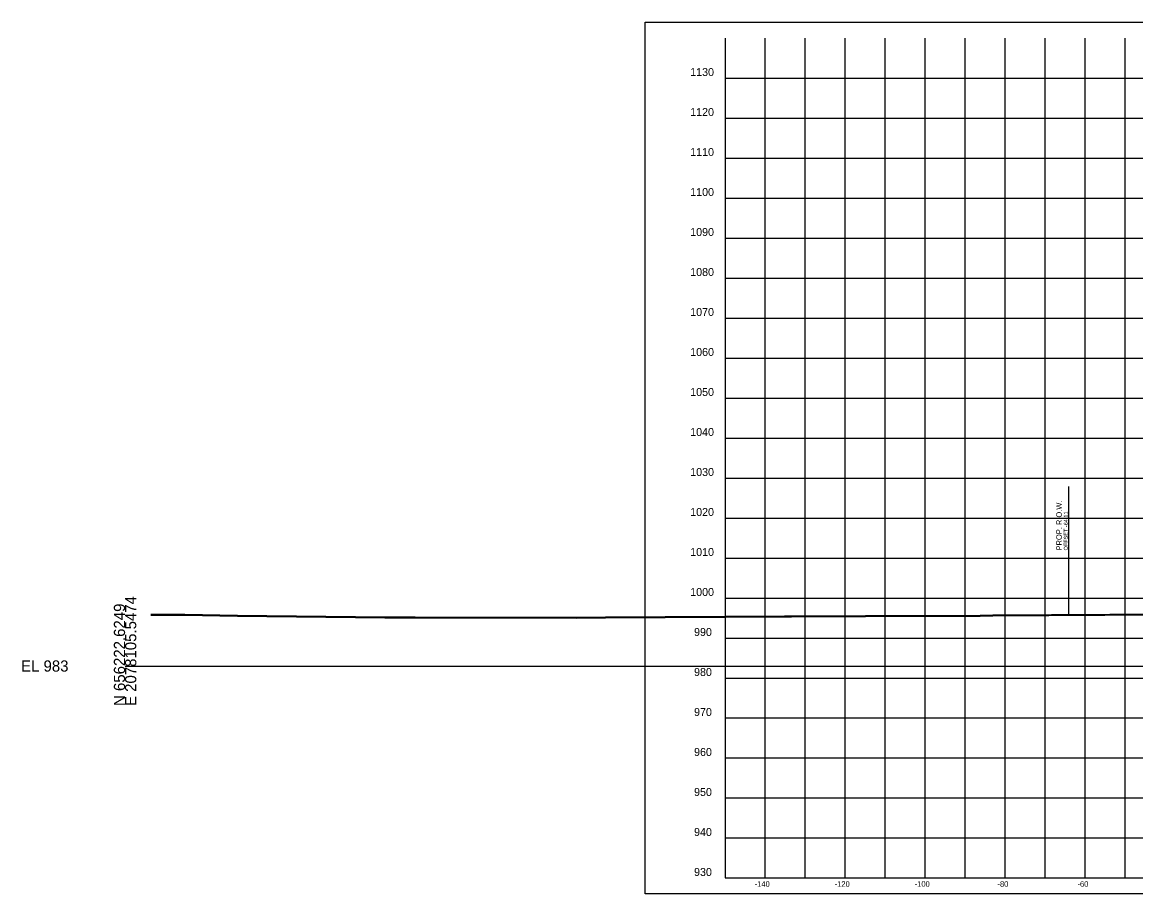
# Model space of a CAD drawing. Extents: x 5868 to 6683, y 2883 to 19120.
# Drawn here: x 5868.1 to 6146.4, y 12888.1 to 13106 of the extents above; entities that cross this region are included whole.
import ezdxf

# ---------------------------------------------------------------- set-up
doc = ezdxf.new("R2010")
doc.units = 0
for name, color, linetype in [('DESIGN - ROW - Right-of-Way and Easement Labels', 7, 'Continuous'), ('DESIGN - ROW - Right-of-Way Linework', 7, 'Continuous'), ('DESIGN - SHEET - Corner Text', 7, 'Continuous'), ('DESIGN - SHEET - Light Grid', 7, 'Continuous'), ('DESIGN - SHEET - Linework', 7, 'Continuous'), ('DESIGN - SHEET - Plot Shape', 7, 'Continuous'), ('SURVEY - GROUND - Bottom of Topsoil Layer', 7, 'Continuous'), ('SURVEY - GROUND - Top of Ground', 7, 'Continuous')]:
    doc.layers.add(name, color=color, linetype=linetype)

msp = doc.modelspace()

# ---------------------------------------------------------------- linework, layer by layer
at = {"layer": 'DESIGN - ROW - Right-of-Way Linework'}
msp.add_line((6129.67, 12957.96), (6129.67, 12989.96), dxfattribs=at)
at = {"layer": 'DESIGN - SHEET - Light Grid'}
msp.add_line((5893.78, 12945.07), (6193.78, 12945.07), dxfattribs=at)
at = {"layer": 'DESIGN - SHEET - Linework'}
for p, q in [((6053.78, 12892.07), (6053.78, 13102.07)), ((6063.78, 12892.07), (6063.78, 13102.07)), ((6073.78, 12892.07), (6073.78, 13102.07)), ((6083.78, 12892.07), (6083.78, 13102.07)), ((6093.78, 12892.07), (6093.78, 13102.07)), ((6103.78, 12892.07), (6103.78, 13102.07)), ((6113.78, 12892.07), (6113.78, 13102.07)), ((6123.78, 12892.07), (6123.78, 13102.07)), ((6133.78, 12892.07), (6133.78, 13102.07)), ((6143.78, 12892.07), (6143.78, 13102.07)), ((6043.78, 13092.07), (6343.78, 13092.07)), ((6043.78, 13082.07), (6343.78, 13082.07)), ((6043.78, 13072.07), (6343.78, 13072.07)), ((6043.78, 13062.07), (6343.78, 13062.07)), ((6043.78, 13052.07), (6343.78, 13052.07)), ((6043.78, 13042.07), (6343.78, 13042.07)), ((6043.78, 13032.07), (6343.78, 13032.07)), ((6043.78, 13022.07), (6343.78, 13022.07)), ((6043.78, 13012.07), (6343.78, 13012.07)), ((6043.78, 13002.07), (6343.78, 13002.07)), ((6043.78, 12992.07), (6343.78, 12992.07)), ((6043.78, 12982.07), (6343.78, 12982.07)), ((6043.78, 12972.07), (6343.78, 12972.07)), ((6043.78, 12962.07), (6343.78, 12962.07)), ((6043.78, 12952.07), (6343.78, 12952.07)), ((6043.78, 12942.07), (6343.78, 12942.07)), ((6043.78, 12932.07), (6343.78, 12932.07)), ((6043.78, 12922.07), (6343.78, 12922.07)), ((6043.78, 12912.07), (6343.78, 12912.07)), ((6043.78, 12902.07), (6343.78, 12902.07))]:
    msp.add_line(p, q, dxfattribs=at)
msp.add_lwpolyline([(6043.78, 13102.07), (6043.78, 12892.07), (6343.78, 12892.07), (6343.78, 13102.07)], dxfattribs=at)
at = {"layer": 'DESIGN - SHEET - Plot Shape'}
msp.add_lwpolyline([(6023.78, 13106.01), (6363.78, 13106.01), (6363.78, 12888.13), (6023.78, 12888.13)], close=True, dxfattribs=at)
at = {"layer": 'SURVEY - GROUND - Bottom of Topsoil Layer'}
for p, q in [((5900.23, 12957.75), (5908.74, 12957.75)), ((5908.74, 12957.75), (5921.88, 12957.55)), ((6110.69, 12957.6), (6154.54, 12957.85)), ((5921.88, 12957.55), (5958.67, 12957.13)), ((5958.67, 12957.13), (5966.3, 12957.1)), ((5966.3, 12957.1), (6006.64, 12957.07)), ((6006.64, 12957.07), (6013.9, 12957.08)), ((6013.9, 12957.08), (6058.64, 12957.33)), ((6058.64, 12957.33), (6060.34, 12957.35)), ((6060.34, 12957.35), (6078.82, 12957.43)), ((6078.82, 12957.43), (6107.49, 12957.55)), ((6107.49, 12957.55), (6110.69, 12957.6))]:
    msp.add_line(p, q, dxfattribs=at)
at = {"layer": 'SURVEY - GROUND - Top of Ground'}
msp.add_lwpolyline([(5900.23, 12958), (5908.74, 12958), (5921.88, 12957.8), (5958.67, 12957.38), (5966.3, 12957.35), (6006.64, 12957.32), (6013.9, 12957.33), (6058.64, 12957.58), (6060.34, 12957.6), (6078.82, 12957.68), (6107.49, 12957.8), (6110.69, 12957.85), (6154.54, 12958.1)], dxfattribs=at)

# ---------------------------------------------------------------- texts
at = {"layer": 'DESIGN - ROW - Right-of-Way and Easement Labels'}
for s, height, p in [('PROP. R.O.W.', 1.4, (6127.92, 12973.96)), ('OFFSET -64.11', 1, (6129.42, 12973.96))]:
    msp.add_text(s, height=height, rotation=90, dxfattribs=at).set_placement(p)
at = {"layer": 'DESIGN - SHEET - Corner Text'}
for s, height, p in [('1130', 2, (6035.03, 13092.57)), ('1120', 2, (6035.03, 13082.57)), ('1110', 2, (6035.03, 13072.57)), ('1100', 2, (6035.03, 13062.57)), ('1090', 2, (6035.03, 13052.57)), ('1080', 2, (6035.03, 13042.57)), ('1070', 2, (6035.03, 13032.57)), ('1060', 2, (6035.03, 13022.57)), ('1050', 2, (6035.03, 13012.57)), ('1040', 2, (6035.03, 13002.57)), ('1030', 2, (6035.03, 12992.57)), ('1020', 2, (6035.03, 12982.57)), ('1010', 2, (6035.03, 12972.57)), ('1000', 2, (6035.03, 12962.57)), ('990', 2, (6036, 12952.57)), ('980', 2, (6036, 12942.57)), ('970', 2, (6036, 12932.57)), ('960', 2, (6036, 12922.57)), ('950', 2, (6036, 12912.57)), ('940', 2, (6036, 12902.57)), ('930', 2, (6036, 12892.57)), ('-140', 1.4, (6051.16, 12889.87)), ('-120', 1.4, (6071.16, 12889.87)), ('-100', 1.4, (6091.16, 12889.87)), ('-80', 1.4, (6111.84, 12889.87)), ('-60', 1.4, (6131.84, 12889.87))]:
    msp.add_text(s, height=height, dxfattribs=at).set_placement(p)
at = {"layer": 'DESIGN - SHEET - Light Grid'}
for s, p in [('N 656222.6249', (5893.78, 12935.07)), ('E 2078105.5474', (5896.58, 12935.07))]:
    msp.add_text(s, height=2.8, rotation=90, dxfattribs=at).set_placement(p)
msp.add_text('EL 983', height=2.8, dxfattribs=at).set_placement((5867.78, 12943.67))

doc.saveas('drawing.dxf')
